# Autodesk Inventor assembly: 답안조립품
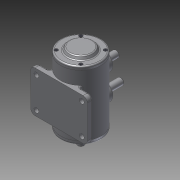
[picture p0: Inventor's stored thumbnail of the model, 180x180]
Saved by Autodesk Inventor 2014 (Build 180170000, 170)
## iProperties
Created: 2014-12
Part Number: 답안조립품
Document SubType Name: Assembly
Designer: Owner
Author: Owner
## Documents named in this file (10)
- C:\Users\Owner\Desktop\441223V1007\답안조립품.iam
- C:\Users\Owner\Desktop\441223V1007\본체.ipt
- C:\Users\Owner\Desktop\441223V1007\M4-소켓머리.ipt
- C:\Users\Owner\Desktop\441223V1007\뒷커버.ipt
- C:\Users\Owner\Desktop\441223V1007\베어링 6203.ipt
- C:\Users\Owner\Desktop\441223V1007\부시.ipt
- C:\Users\Owner\Desktop\441223V1007\슬라이더.ipt
- C:\Users\Owner\Desktop\441223V1007\앞커버.ipt
- C:\Users\Owner\Desktop\441223V1007\오일실.ipt
- C:\Users\Owner\Desktop\441223V1007\축.ipt
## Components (11 placed, 3 different names)
1. 9-M4-소켓머리:1
2. 7-베어링 6203:1
3. 8-오일실:1
4. 7-베어링 6203:2
5. 9-M4-소켓머리:2
6. 9-M4-소켓머리:3
7. 9-M4-소켓머리:4
8. 9-M4-소켓머리:5
9. 9-M4-소켓머리:6
10. 9-M4-소켓머리:7
11. 9-M4-소켓머리:8
